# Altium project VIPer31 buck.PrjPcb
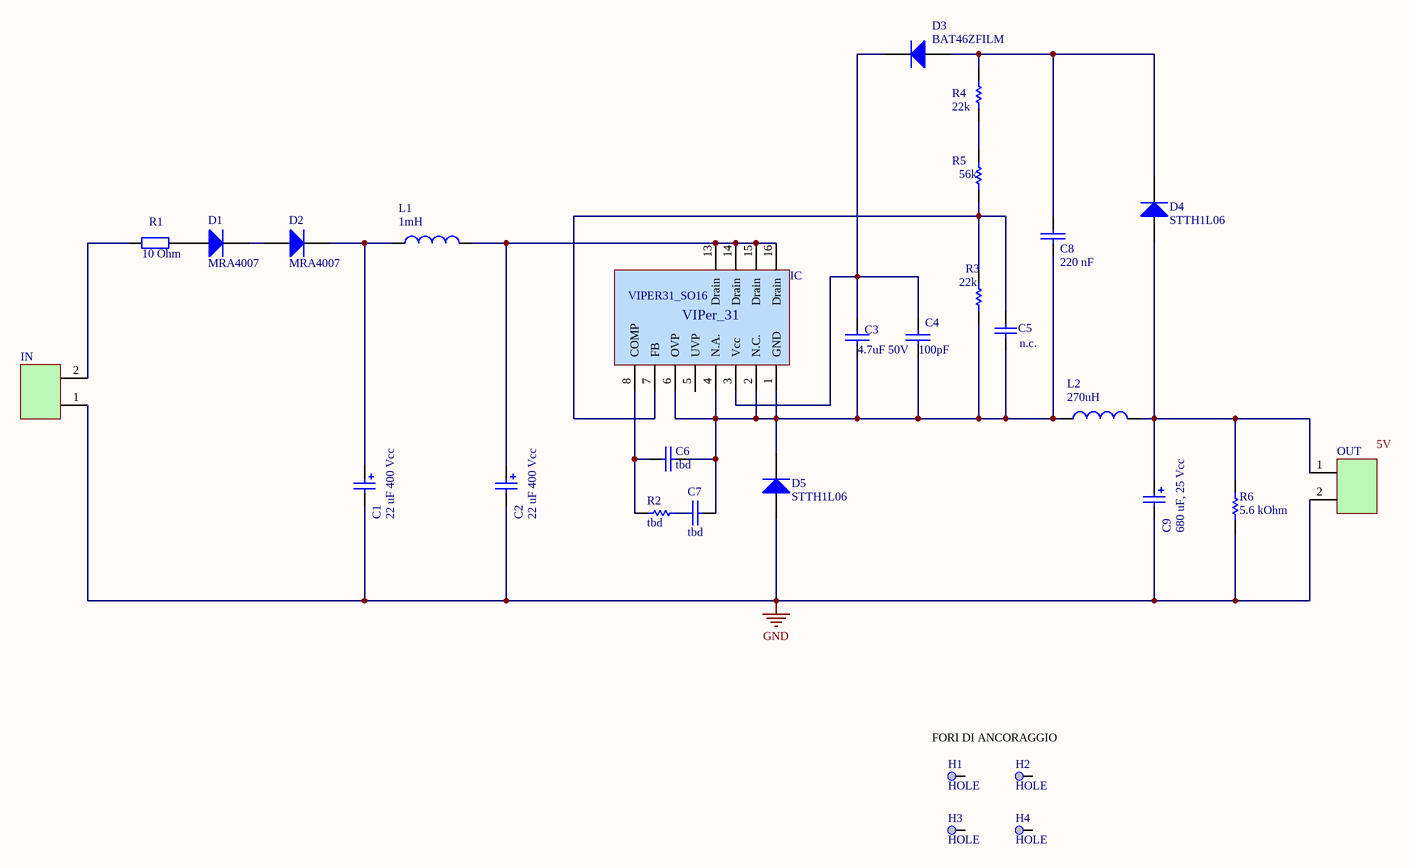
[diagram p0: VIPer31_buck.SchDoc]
1 sheet, 29 parts. Net scope: global (net labels, ports and power ports of the same name join across sheets).
Board file: VIPer31 Buck.PcbDoc

## Sheet VIPer31_buck.SchDoc
size A3; PageSetup: Record=PageOptions¦CenterHorizontal=True¦CenterVertical=True¦PrintScale=0.73¦XCorrection=1.00¦YCorrection=1.00¦PrintKind=1¦BorderSize=5000000¦LeftOffset=0¦BottomOffset=0¦Orientation=2¦PaperLength=1000¦PaperWidth=1000¦Scale=100¦PaperSource=7¦PrintQuality=-3¦MediaType=1¦DitherType=10¦PrintScaleMode=1¦PaperKind=A4¦PaperIndex=9

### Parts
C1  22 uF 400 Vcc  [CAPOL-5X10]
C2  22 uF 400 Vcc  [CAPOL-5X10]
C3  4.7uF 50V  [R-1206-B2]
C4  100pF  [R-0805-B2]
C5  n.c.  [R-0603-B]
C6  tbd  [R-0603-B2]
C7  tbd  [R-0603-B2]
C8  220 nF  [R-1206-B2]
C9  680 uF, 25 Vcc  [CAPOL-3.5X8]
D1  MRA4007  [SMA-2]
D2  MRA4007  [SMA-2]
D3  BAT46ZFILM  [SOD-123]
D4  STTH1L06  [SMA-2]
D5  STTH1L06  [SMA-2]
H1  HOLE  [FORO]
H2  HOLE  [FORO]
H3  HOLE  [FORO]
H4  HOLE  [FORO]
IC  VIPER31_SO16  [SO-16N_2]
IN  input connector  [SM.2VITE]  (value not drawn)
L1  1mH  [1W-VER]
L2  270uH  [CAPOL-6X11]
OUT  output connector  [SM.2VITE]  (value not drawn)
R1  10 Ohm  [2W-VER]
R2  tbd  [R-0603-B2]
R3  22k  [R-1206-B2]
R4  22k  [R-0603-B2]
R5  56k  [R-0603-B2]
R6  5.6 kOhm  [R-0805-B2]

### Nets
GND: C1.2 C2.2 C9.2 D5.1(A) IN.1 OUT.2 R6.1
NetC1_1: C1.1 D2.2(K) L1.1
NetC2_1: C2.1 IC.13(Drain) IC.14(Drain) IC.15(Drain) IC.16(Drain) L1.2
NetC3_1: C3.1 C4.1 D3.2(K) IC.3(Vcc)
NetC3_2: C3.2 C4.2 C5.1 C6.2 C7.2 C8.2 D5.2(K) IC.1(GND) IC.2(N.C.) IC.4(N.A.) IC.6(OVP) L2.1 R3.1
NetC5_2: C5.2 IC.7(FB) R3.2 R5.2
NetC6_1: C6.1 IC.8(COMP) R2.2
NetC7_1: C7.1 R2.1
NetC8_1: C8.1 D3.1(A) D4.2(K) R4.2
NetC9_1: C9.1 D4.1(A) L2.2 OUT.1 R6.2
NetD1_1: D1.1(A) R1.1
NetD1_2: D1.2(K) D2.1(A)
NetIN_2: IN.2 R1.2
NetR4_1: R4.1 R5.1

Not connected (* = marked no-connect by the designer): H1 1; H2 1; H3 1; H4 1; IC 5(UVP)

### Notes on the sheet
- FORI DI ANCORAGGIO
- Labels drawn without touching a wire or pin: 5V

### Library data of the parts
C1 C2 = Cap Pol1: Polarized Capacitor (Radial); Part number: 400BXC68MEFC18X25; Value: 68 uF +/-20%, 400 Vcc, +105°C
C3 = CAP: 1 nF 630 V multi layer capacitor; Part number: C3216C0G2J102J085AA; Value: 1 nF 630 Vdc
C4 = CAP: 100 pF 250 Vdc multi layer capacitor; Part number: CGA3E3C0G2E101J080AA; Value: 100 pF +/-5%, 250 Vdc
C5 = Cap: Capacitor; Value: 100pF
C6 = CAP: 1 nF 200 Vdc multi layer capacitor; Part number: C0603C102J2GACAUTO; Value: 1 nF +/-5%, 200 Vdc
C7 = CAP: NC
C8 = CAP: 100nF ±10%, 25 Vcc, MLCC; Part number: C0603C104K3RACTU
C9 = Cap Pol1: 470 uF +/-20%, 35 Vcc, +105°C; Part number: 25ZLH470MEFC10X12.5
D1 D2 = Diode 1N4007: 1 Amp General Purpose Rectifier
D3 = Diode: Silicon Diode, 1 A, 1000 V; Value: MRA4007T3G
D4 = Diode: small signal diode; Part number: STPS1150A; Value: 1 A, 150 V
D5 = Diode: Schottky diode, 10A, 200 V; Part number: STPS2200UF
IC = VIPER31_SO16: Integrato
IN OUT = M.2VITE: Morsetti
L1 L2 = Inductor: FIXED IND 3.3UH 3.23A 33 MOHM; Part number: 74404043033A
R1 = Res2: Part number: NTPA7100LBMB0
R2 R4 R5 = Res1: Not connected
R3 = Res1: 0Ω, 0.25W, pkg 0603, serie CRCW; Part number: CRCW06030000Z0EAHP; Value: 0 Ohm, 0.25W
R6 = Res1: 6.8 kOhm +/-1% 0.125W, 0805 Panasonic; Part number: ERJP08J105V; Value: 1MOhm +/-5%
